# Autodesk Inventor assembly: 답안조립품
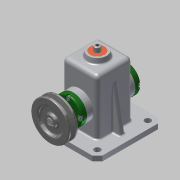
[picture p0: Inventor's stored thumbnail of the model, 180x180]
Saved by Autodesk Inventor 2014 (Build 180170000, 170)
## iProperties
Created: 2016-02
Part Number: 답안조립품
Document SubType Name: Assembly
Designer: 406-05
Author: 406-05
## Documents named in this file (16)
- C:\Users\406-05\Desktop\460211V1026\답안조립품.iam
- C:\Users\406-05\Desktop\460211V1026\1-본체.ipt
- C:\Users\406-05\Desktop\460211V1026\V벨트풀리.ipt
- C:\Users\406-05\Desktop\460211V1026\고정핀 1.2 x 10.ipt
- C:\Users\406-05\Desktop\460211V1026\뒤커버.ipt
- C:\Users\406-05\Desktop\460211V1026\링크.ipt
- C:\Users\406-05\Desktop\460211V1026\멈춤나사 M3x8.ipt
- C:\Users\406-05\Desktop\460211V1026\베어링 12 x 32 x 10.ipt
- C:\Users\406-05\Desktop\460211V1026\볼트 M4 x 12.ipt
- C:\Users\406-05\Desktop\460211V1026\부시.ipt
- C:\Users\406-05\Desktop\460211V1026\슬라이드.ipt
- C:\Users\406-05\Desktop\460211V1026\앞커버.ipt
- C:\Users\406-05\Desktop\460211V1026\오일실 12 25 7.ipt
- C:\Users\406-05\Desktop\460211V1026\키 4 x 4 x 10.ipt
- C:\Users\406-05\Desktop\460211V1026\편심축.ipt
- C:\Users\406-05\Desktop\460211V1026\핀 5 x 18.ipt
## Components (12 placed, 5 different names)
1. 1-본체:1 — 각도:3, 각도:4
2. V벨트풀리:1 — 각도:2, 각도:5
3. 고정핀 1.2 x 10:1 — 강체:1
4. 핀 5 x 18:1 — 강체:1
5. ISO 4762 M4 x 12:2 — 각도:3
6. ISO 4762 M4 x 12:3
7. ISO 4762 M4 x 12:4
8. ISO 4762 M4 x 12:5
9. ISO 4762 M4 x 12:1 — 각도:4
10. ISO 4762 M4 x 12:6
11. ISO 4762 M4 x 12:7
12. ISO 4762 M4 x 12:8
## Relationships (5: Angle 4, WeldJoint 1)
- 각도:2 [Angle]: V벨트풀리:1
- 각도:3 [Angle]: 1-본체:1 ↔ ISO 4762 M4 x 12:2
- 각도:4 [Angle]: 1-본체:1 ↔ ISO 4762 M4 x 12:1
- 각도:5 [Angle]: V벨트풀리:1
- 강체:1 [WeldJoint]: 고정핀 1.2 x 10:1 ↔ 핀 5 x 18:1
